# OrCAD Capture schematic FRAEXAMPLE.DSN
size A; title: FRA Example; rev: A; company: EMA Design Automation; note: EMA-12345678; note: 225 Tech Park Drive; note: Rochester, NY, 14623
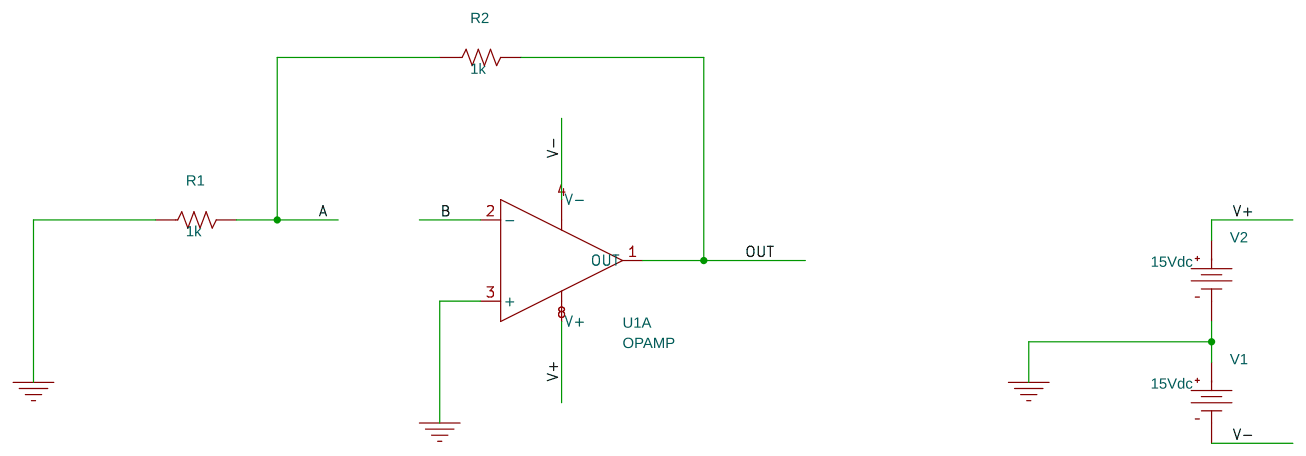
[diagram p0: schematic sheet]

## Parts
R1  1k  [AXRC05]
R2  1k  [AXRC05]
U1  OPAMP  [DIP.100/8/W.300/L.425]  (section A)
V1  VDC
V2  VDC

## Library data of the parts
R1 R2 = R
U1 = OPAMP1A
V1 V2 = VDC: DC: 15Vdc

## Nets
0: R1.1 U1.3(+) V1.0(+) V2.1(-)
A: R1.2 R2.1
B: U1.2(-)
OUT: R2.2 U1.1(OUT)
V+: U1.8(V+) V2.0(+)
V-: U1.4(V-) V1.1(-)
